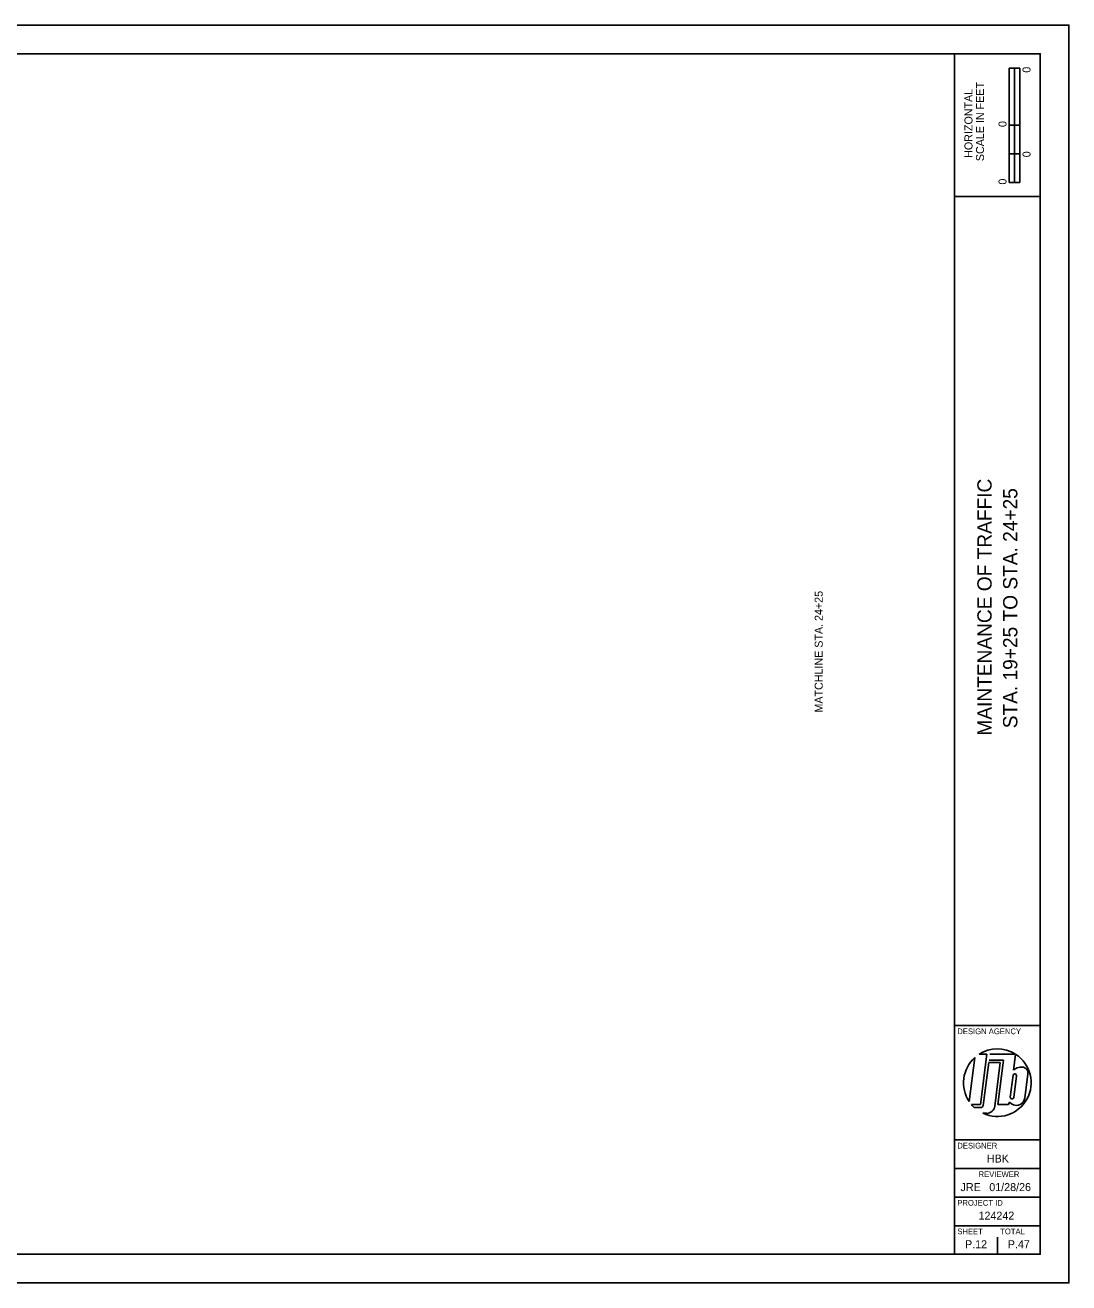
# Model space of a CAD drawing. Extents: x -2.5 to 34, y 0 to 22.
# Drawn here: x 15.75 to 34, y 0 to 22 of the extents above; entities that cross this region are included whole.
import ezdxf

# ---------------------------------------------------------------- set-up
doc = ezdxf.new("R2010")
doc.units = 0
for name, color, linetype in [('Default', 7, 'Continuous'), ('SH_Border', 7, 'Continuous'), ('SH_Cut_Line', 7, 'Continuous'), ('SH_Data', 7, 'Continuous')]:
    doc.layers.add(name, color=color, linetype=linetype)

msp = doc.modelspace()

# ---------------------------------------------------------------- linework, layer by layer
at = {"layer": 'SH_Border'}
for p, q in [((32, 0.5), (32, 21.5)), ((32, 19), (33.5, 19)), ((32, 4.5), (33.5, 4.5)), ((32, 2.5), (33.5, 2.5)), ((32, 2), (33.5, 2)), ((32, 1.5), (33.5, 1.5)), ((32, 1), (33.5, 1))]:
    msp.add_line(p, q, dxfattribs=at)
msp.add_lwpolyline([(1.5, 21.5), (33.5, 21.5), (33.5, 0.5), (1.5, 0.5)], close=True, dxfattribs=at)
at = {"layer": 'SH_Cut_Line'}
msp.add_lwpolyline([(0, 0), (34, 0), (34, 22), (0, 22)], close=True, dxfattribs=at)
at = {"layer": 'SH_Data'}
for p, q in [((32.957, 19.25), (32.957, 21.25)), ((33.144, 21.25), (32.957, 21.25)), ((32.957, 20.25), (32.957, 21.25)), ((32.957, 21.25), (33.05, 21.25)), ((33.05, 21.25), (33.051, 21.25)), ((33.051, 21.25), (33.051, 20.25)), ((33.144, 21.25), (33.144, 19.25)), ((33.051, 20.25), (32.957, 20.25)), ((33.143, 20.25), (33.05, 20.25)), ((33.05, 20.25), (33.05, 19.75)), ((33.143, 19.75), (33.143, 20.25)), ((33.05, 19.75), (32.957, 19.75)), ((32.957, 19.75), (32.957, 19.25)), ((33.05, 19.25), (33.05, 19.75)), ((33.05, 19.75), (33.143, 19.75)), ((33.144, 19.25), (32.957, 19.25)), ((32.957, 19.25), (33.05, 19.25)), ((32.432, 3.998), (32.567, 3.998)), ((32.567, 3.998), (32.456, 3.118)), ((32.617, 4), (33.065, 4)), ((33.07, 3.996), (33.035, 3.72)), ((32.356, 3.94), (32.259, 3.171)), ((32.504, 3.104), (32.599, 3.855)), ((32.599, 3.855), (32.801, 3.855)), ((32.856, 3.896), (32.604, 3.896)), ((32.801, 3.855), (32.704, 3.089)), ((32.758, 3.118), (32.856, 3.896)), ((33.024, 3.631), (32.976, 3.25)), ((33.036, 3.243), (33.084, 3.624)), ((33.283, 3.648), (33.231, 3.237)), ((32.75, 3.5), (32.75, 3.5)), ((32.456, 3.118), (32.299, 3.118)), ((32.947, 3.118), (32.758, 3.118)), ((32.964, 3.161), (32.947, 3.118)), ((32.347, 3.068), (32.462, 3.068)), ((32.564, 2.966), (32.498, 2.966)), ((32.375, 0.675), (32.375, 0.675)), ((32.75, 0.5), (32.75, 0.8))]:
    msp.add_line(p, q, dxfattribs=at)
for centre, radius, start, end in [((32.75, 3.5), 0.591, 57.726, 122.5688), ((32.75, 3.5), 0.591, 244.7646, 57.1575), ((32.75, 3.5), 0.591, 131.8253, 213.7822), ((33.17, 3.586), 0.19, 105.9444, 135.0487), ((33.164, 3.6), 0.175, 66.6782, 105.4185), ((33.177, 3.669), 0.108, 349.2072, 58.7163), ((33.054, 3.628), 0.0301, 352.3298, 173.2777), ((32.75, 3.5), 0.591, 220.2786, 227.0158), ((32.462, 3.109), 0.0417, 270, 352.8038), ((32.564, 3.106), 0.141, 270, 352.8038), ((33.081, 3.255), 0.151, 218.6264, 353.0883), ((33.006, 3.246), 0.0301, 172.3335, 353.274)]:
    msp.add_arc(centre, radius, start, end, dxfattribs=at)

# ---------------------------------------------------------------- texts
at = {"layer": 'Default'}
msp.add_text('MATCHLINE STA. 24+25', height=0.14, rotation=90, dxfattribs=at).set_placement((29.696, 9.976))
at = {"layer": 'SH_Data'}
for s, height, p in [('0', 0.14, (33.33, 21.168)), ('SCALE IN FEET', 0.14, (32.517, 19.621)), ('HORIZONTAL', 0.14, (32.315, 19.679)), ('0', 0.14, (32.91, 20.218)), ('0', 0.14, (33.33, 19.689)), ('0', 0.14, (32.91, 19.211)), ('MAINTENANCE OF TRAFFIC', 0.25, (32.65, 9.572)), ('STA. 19+25 TO STA. 24+25', 0.25, (33.1, 9.701))]:
    msp.add_text(s, height=height, rotation=90, dxfattribs=at).set_placement(p)
for s, height, p in [('DESIGN AGENCY', 0.1, (32.05, 4.35)), ('DESIGNER', 0.1, (32.05, 2.35)), ('HBK', 0.14, (32.567, 2.105)), ('REVIEWER', 0.1, (32.422, 1.85)), ('JRE', 0.14, (32.107, 1.605)), ('01/28/26', 0.14, (32.609, 1.605)), ('PROJECT ID', 0.1, (32.05, 1.35)), ('124242', 0.14, (32.421, 1.105)), ('SHEET', 0.1, (32.05, 0.85)), ('TOTAL', 0.1, (32.8, 0.85)), ('P.12', 0.14, (32.185, 0.605)), ('P.47', 0.14, (32.933, 0.605))]:
    msp.add_text(s, height=height, dxfattribs=at).set_placement(p)

doc.saveas('drawing.dxf')
